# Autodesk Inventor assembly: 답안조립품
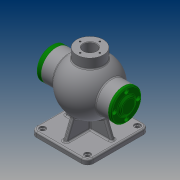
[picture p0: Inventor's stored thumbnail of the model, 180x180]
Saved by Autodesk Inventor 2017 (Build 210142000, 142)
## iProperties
Part Number: 답안조립품
Material: 일반
Document SubType Name: Assembly
Designer: 13
Author: 13
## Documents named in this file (6)
- C:\Users\13\Desktop\480414V1001\답안조립품.iam
- C:\Users\13\Desktop\480414V1001\본체.ipt
- C:\Users\13\Desktop\480414V1001\뒤커버.ipt
- C:\Users\13\Desktop\480414V1001\앞커버.ipt
- C:\Users\13\Desktop\480414V1001\베어링 6202.ipt
- 베어링 6202.ipt
